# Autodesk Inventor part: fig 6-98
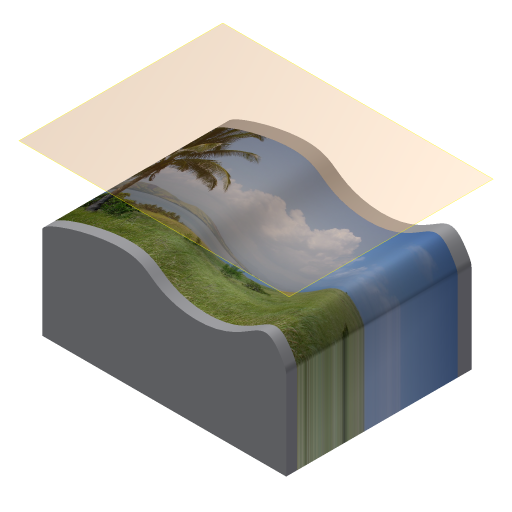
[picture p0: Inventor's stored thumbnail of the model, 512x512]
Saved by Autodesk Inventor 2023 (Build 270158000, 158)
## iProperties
Created: 2012-08
Part Number: fig 6-98
Material: Generic
Document SubType Name: Modeling
Designer: CADCIM
Density: 1 g/cm^3
Appearance: Default
Author: CADCIM
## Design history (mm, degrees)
sketch "Sketch1"
  geometry: L1 (0, 0)-(0, 12.146); L2 (32.23, 12.146)-(32.23, 0); L3 (32.23, 0)-(0, 0); 5 further points
  constraints: 6 end point, 1 parallel, 1 perpendicular, 1 vertical, 7 other
extrude "Extrusion1" new body sketch "Sketch1" distance "d0" = 24.5; taper "d1" = 0 deg
workplane "Work Plane1"
fillet "Fillet1" dims "d19" = 2
sketch "Sketch2"
  geometry: L1 (-33.343, 22.666)-(0.669, 22.666); L2 (0.669, 22.666)-(0.669, 1.409); L3 (0.669, 1.409)-(-33.343, 1.409); L4 (-33.343, 1.409)-(-33.343, 22.666); 1 other entity
  constraints: 2 other
feature "Decal1" sketch "Sketch2"
body "Solid1"
node "Image1"
other parameters: "d2" = 22
